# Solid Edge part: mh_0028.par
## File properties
Title: handle_f
Author: edge
Template: normal.par
Last saved by: edge
Revision: 35
Application: Solid Edge
Density: 0.001200 g/mm^3
Accuracy: 0.99
非切断部品: False
文書内容のタイプ: 0
Material: ＡＢＳ
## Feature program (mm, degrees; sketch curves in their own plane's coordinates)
sketch for "unnamed Protrusion 1" plane through (0, 0, 0) normal (0, 0, 1) x-axis (1, 0, 0)
  line (-30, 65) -> (30, 65)
  line (30, 65) -> (30, -15)
  line (30, -15) -> (-30, -15)
  line (-30, -15) -> (-30, 65)
extrude "unnamed Protrusion 1" add finite 26 along -normal
thinwall "Thinwall_1"  Thickness = 1 mm
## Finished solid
Body 1: solid body, 11 faces, 24 edges, 16 vertices.
  Faces by surface: plane 11
  Edges by curve: line 24
Bounding box of the edges (mm): 60.000 x 80.000 x 26.000, from (-30, -15, -26) to (30, 65, 0).
Planar faces by outward normal: +x 2, +y 2, +z 2, -x 2, -y 2, -z 1
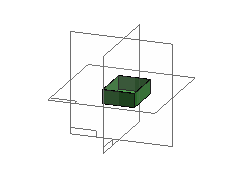
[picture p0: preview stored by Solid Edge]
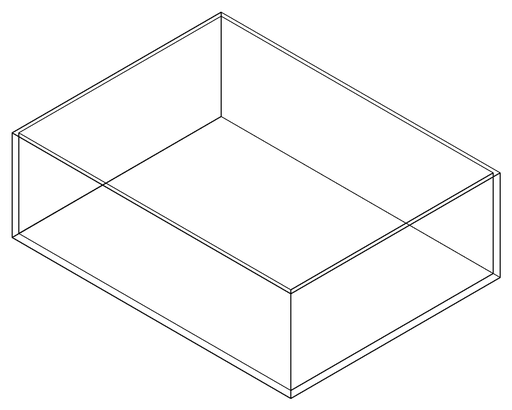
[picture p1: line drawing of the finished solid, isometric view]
